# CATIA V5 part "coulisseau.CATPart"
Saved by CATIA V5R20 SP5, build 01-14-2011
Part number: coulisseau
Bounding box of the stored display mesh (mm): x -7 to 15, y 82 to 98, z 94 to 106
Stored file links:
  U:\2A\IAO\ThinkMotion\coulisseau.CATPart
  U:\2A\IAO\ThinkMotion\MECANISME 1517.CATProduct
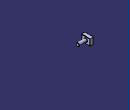
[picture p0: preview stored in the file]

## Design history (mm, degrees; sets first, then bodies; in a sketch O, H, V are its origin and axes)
Set1
  Plane1 "Plan_ref": linked copy from another document
  Point1: linked copy from another document
Body1 (main body)
  Sketch1 on Plane1, origin (0, 0, 0), H (0, 1, 0), V (0, 0, 1)
    line L1 (82, 106) -> (98, 106)
    line L2 (98, 106) -> (98, 94)
    line L3 (98, 94) -> (82, 94)
    line L4 (82, 94) -> (82, 106)
    reference projected point E1 (90, 100) from Point1
    reference projected point E2 (90, 100) from Point1
    reference projected point E3 (90, 100) from Point1
    reference projected point E4 (90, 100) from Point1
    distance E1 L2 = 8
    distance E2 L4 = 8
    distance L1 E3 = 6
    distance E4 L3 = 6
    horizontal: L1 H, L3 H
    vertical: L2 V, L4 V
  Pad1: profile Sketch1, direction (-1, 0, 0), length 7
  Sketch2 on end face of Pad1, origin (-7, 0, 0), H (0, -1, 0), V (0, 0, 1)
    circle A1 centre (-90, 100) radius 3
    point P1 (-90, 100)
    reference projected point E1 (-90, 100) from Point1
    radius A1 = 3
    coincidence: P1 E1
  Pad2: profile Sketch2, direction (1, 0, 0), length 22
  Fillet1: radius 0.5, on start face of Pad1; face of Pad2; face of Pad2 from Sketch2.A1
